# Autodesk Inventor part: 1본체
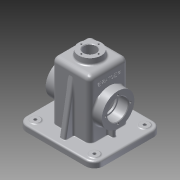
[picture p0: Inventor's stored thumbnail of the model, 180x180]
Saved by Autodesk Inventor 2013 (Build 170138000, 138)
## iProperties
Created: 2016-01
Part Number: 1본체
Material: 알루미늄 6061
Document SubType Name: Modeling
Designer: Administrator
Density: 2.71 g/cm^3
Mass: 867.692 g
Surface Area: 918.115 cm^2
Volume: 320.182 cm^3
Author: Administrator
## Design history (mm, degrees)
sketch "스케치1"
  geometry: L1 (-65, 57.5)-(65, 57.5); L2 (65, 57.5)-(65, -57.5); L3 (65, -57.5)-(-65, -57.5); L4 (-65, -57.5)-(-65, 57.5); 3 further points
  constraints: 8 end point, 2 midpoint, 2 parallel, 1 horizontal, 1 horizontal alignment, 1 perpendicular, 1 vertical alignment
  dimensions: "d0" = 130 distance of L1.start L1.end; "d2" = 115 distance of L1.end L2.end
extrude "돌출1" new body sketch "스케치1" distance "d3" = 10; taper "d4" = 0 deg
fillet "모깎기1" dims "d5" = 15
sketch "스케치2"
  geometry: L1 (-60, -52.5)-(60, -52.5); L2 (60, -52.5)-(60, 52.5); L3 (60, 52.5)-(-60, 52.5); L4 (-60, 52.5)-(-60, -52.5); 3 further points
  constraints: 8 end point, 2 midpoint, 2 parallel, 1 horizontal, 1 horizontal alignment, 1 perpendicular, 1 vertical alignment
  dimensions: "d6" = 105 distance of L3.end L1.start; "d8" = 120 distance of L2.end L3.end
extrude "돌출2" join sketch "스케치2" distance "d9" = 2; taper "d10" = 0 deg
fillet "모깎기2" dims "d11" = 10
sketch "스케치3"
  geometry: C1 r 7.5 at (-50, 42.5); C2 r 7.5 at (-50, -42.5); C3 r 7.5 at (50, -42.5); C4 r 7.5 at (50, 42.5); A1 r 15 centre (50, 42.5) between (65, 42.5) and (50, 57.5) reference; A2 r 15 centre (-50, 42.5) between (-50, 57.5) and (-65, 42.5) reference; A3 r 15 centre (-50, -42.5) between (-65, -42.5) and (-50, -57.5) reference; A4 r 15 centre (50, -42.5) between (50, -57.5) and (65, -42.5) reference; 1 further point
  constraints: 4 centre point, 4 coincident
  dimensions: "d12" = 15 diameter of C1; "d13" = 15 diameter of C2; "d14" = 15 diameter of C3; "d15" = 15 diameter of C4
extrude "돌출3" join sketch "스케치3" distance "d16" = 1; taper "d17" = 0 deg
hole "구멍1" diameter "d20" = 5; stored, may be unused: countersink angle "d24" = 90 deg, drill point angle "d26" = 118 deg; dims "d18" = 10, "d19" = 10, "d21" = 6, "d22" = 4, "d23" = 2, "d25" = 8
hole "구멍2" diameter "d29" = 5; stored, may be unused: countersink angle "d33" = 90 deg, drill point angle "d35" = 118 deg; dims "d27" = 10, "d28" = 10, "d30" = 6, "d31" = 4, "d32" = 2, "d34" = 8
hole "구멍3" diameter "d38" = 5; stored, may be unused: countersink angle "d42" = 90 deg, drill point angle "d44" = 118 deg; dims "d36" = 10, "d37" = 10, "d39" = 6, "d40" = 4, "d41" = 2, "d43" = 8
hole "구멍4" diameter "d47" = 5; stored, may be unused: countersink angle "d51" = 90 deg, drill point angle "d53" = 118 deg; dims "d45" = 10, "d46" = 10, "d48" = 6, "d49" = 4, "d50" = 2, "d52" = 8
sketch "스케치4"
  geometry: L1 (-32.5, 32.5)-(32.5, 32.5); L2 (32.5, 32.5)-(32.5, -32.5); L3 (32.5, -32.5)-(-32.5, -32.5); L4 (-32.5, -32.5)-(-32.5, 32.5); 3 further points
  constraints: 8 end point, 2 midpoint, 2 parallel, 1 horizontal, 1 horizontal alignment, 1 perpendicular, 1 vertical alignment
  dimensions: "d54" = 65 distance of L1.start L1.end; "d56" = 65 distance of L1.end L2.end
extrude "돌출4" join sketch "스케치4" distance "d57" = 98; taper "d58" = 0 deg
sketch "스케치6"
  geometry: C1 r 20 at (0, 0); 1 further point
  constraints: 2 coincident, 1 centre point
  dimensions: "d63" = 40 diameter of C1
extrude "돌출6" join sketch "스케치6" distance "d64" = 10; taper "d65" = -5 deg
fillet "모깎기3" dims "d66" = 8
fillet "모깎기4" dims "d67" = 8
sketch "스케치12"
  geometry: L1 (57.5, 10)-(57.5, 0) reference; L2 (57.5, 0)-(52.5, 0) reference; L3 (52.5, 0)-(52.5, -2) reference; L4 (52.5, -2)-(-52.5, -2) reference; L5 (-52.5, -2)-(-52.5, 0) reference; L6 (-52.5, 0)-(-57.5, 0) reference; L7 (-57.5, 0)-(-57.5, 10) reference; L8 (-57.5, 10)-(-32.5, 10) reference; L9 (-32.5, 10)-(-32.5, 100) reference; L10 (-24.5, 108)-(-20, 108) reference; L11 (-20, 108)-(-19.125, 118) reference; L12 (-19.125, 118)-(19.125, 118) reference; L13 (19.125, 118)-(20, 108) reference; L14 (20, 108)-(24.5, 108) reference; L15 (32.5, 100)-(32.5, 10) reference; L16 (32.5, 10)-(57.5, 10) reference; L17 (-31.102, 103)-(-47.5, 10); L18 (-31.102, 103)-(-31.102, 10); L19 (42.5, 10)-(-42.5, 10) reference; L20 (-57.5, 0)-(-57.5, 10) reference; A1 r 8 centre (-24.5, 100) between (-24.5, 108) and (-32.5, 100) reference; A2 r 8 centre (24.5, 100) between (32.5, 100) and (24.5, 108) reference; 1 further point
  constraints: 4 end point, 2 point on line, 1 vertical
  dimensions: "d122" = 10 distance of L17.end L7.end; "d123" = 10 deg angle of L17 L20; "d124" = 93 distance of L17.start L18.end
extrude "돌출9" join sketch "스케치12" stored distance "d125" = 10; taper "d126" = 0 deg
sketch "스케치7"
  geometry: L1 (27.5, -27.5)-(-27.5, -27.5); L2 (-27.5, -27.5)-(-27.5, 27.5); L3 (-27.5, 27.5)-(27.5, 27.5); L4 (27.5, 27.5)-(27.5, -27.5); 3 further points
  constraints: 8 end point, 2 midpoint, 2 parallel, 1 horizontal, 1 horizontal alignment, 1 perpendicular, 1 vertical alignment
  dimensions: "d68" = 55 distance of L1.end L2.end; "d70" = 55 distance of L1.start L1.end
extrude "돌출7" cut sketch "스케치7" distance "d71" = 105; taper "d72" = 0 deg
fillet "모깎기5" dims "d73" = 3
fillet "모깎기6" dims "d74" = 3
hole "구멍5" diameter "d77" = 21; stored, may be unused: countersink angle "d81" = 90 deg, drill point angle "d83" = 118 deg; dims "d75" = 10, "d76" = 10, "d78" = 6, "d79" = 4, "d80" = 2, "d82" = 8
sketch "스케치8"
  geometry: L1 (12, 67)-(12, -18) reference; L2 (0, -18)-(0, 67) reference; C1 r 27.5 at (-43, 24.5); 2 further points
  constraints: 1 centre point, 1 horizontal alignment, 1 midpoint
  dimensions: "d84" = 55 diameter of C1; "d156" = 55 distance from line of L1 C1.centre
extrude "돌출8" join sketch "스케치8" distance "d85" = 15; taper "d86" = 0 deg
hole "구멍6" diameter "d89" = 30; stored, may be unused: countersink angle "d93" = 90 deg, drill point angle "d95" = 0 deg; dims "d87" = 10, "d88" = 10, "d90" = 6, "d91" = 35, "d92" = 17, "d94" = 20
sketch "스케치9"
  geometry: C1 r 17.5 at (0, 0) reference; 2 further points
  constraints: 1 horizontal alignment
  dimensions: "d96" = 21 distance of C1.centre point (21, 0)
hole "구멍7" sketch "스케치9" at (21, 0) diameter "d97" = 3.242; stored, may be unused: countersink angle "d101" = 90 deg, drill point angle "d103" = 118 deg; dims "d98" = 8, "d99" = 35, "d100" = 17, "d102" = 10
sketch "스케치10"
  geometry: C1 r 10.5 at (0, 0) reference; 1 further point
  constraints: 1 horizontal alignment
  dimensions: "d107" = 14.5 distance of C1.centre point (-14.5, 0)
hole "구멍8" sketch "스케치10" at (-14.5, 0) diameter "d108" = 2.459; stored, may be unused: countersink angle "d112" = 90 deg, drill point angle "d114" = 118 deg; dims "d109" = 7, "d110" = 35, "d111" = 17, "d113" = 9
sketch "스케치14"
  geometry: L1 (-18, 5.375)-(-18, 43.625) reference; A1 r 27.5 centre (47, 24.5) between (34.51, 49) and (34.51, 0) reference; 2 further points
  constraints: 1 horizontal alignment, 1 other
  dimensions: "d131" = 27 distance from line of L1 point (9, 24.5)
feature "엠보싱1" sketch "스케치14" dims "d132" = 0.5, "d133" = 0
chamfer "모따기1" distance "d134" = 1; stored, may be unused: second distance "d135" = 2, angle "d136" = 45 deg
fillet "모깎기7" dims "d137" = 0.3
fillet "모깎기8" dims "d138" = 3
fillet "모깎기9" dims "d139" = 3
fillet "모깎기10" dims "d140" = 3
sketch "스케치15"
  geometry: L1 (-27.5, 100)-(-27.5, 68) reference; L2 (-27.5, 68)-(-30.5, 68) reference; L3 (-30.5, 68)-(-30.5, 70.2) reference; L4 (-30.8, 70.5)-(-46.5, 70.5) reference; L5 (-46.5, 70.5)-(-47.5, 71.5) reference; L6 (-47.5, 71.5)-(-47.5, 72.379) reference; L7 (-47.5, 72.379)-(-37.5, 72.379) reference; L8 (-37.5, 72.379)-(-36.526, 74) reference; L9 (-36.526, 74)-(-37.5, 75.621) reference; L10 (-37.5, 75.621)-(-47.5, 75.621) reference; L11 (-47.5, 75.621)-(-47.5, 80.5) reference; L12 (-47.5, 80.5)-(-32.5, 80.5) reference; L13 (-32.5, 80.5)-(-32.5, 92.971) reference; L14 (-32.5, 92.971)-(-33, 92.971) reference; L15 (-33, 92.971)-(-33, 93.385) reference; L16 (-33, 93.385)-(-32.5, 93.385) reference; L17 (-32.5, 93.385)-(-32.5, 100) reference; L18 (-24.5, 108)-(-20, 108) reference; L19 (-20, 108)-(-19.125, 118) reference; L20 (-19.125, 118)-(-15.73, 118) reference; L21 (-15.73, 118)-(-15.73, 109) reference; L22 (-15.73, 109)-(-14.5, 108.261) reference; L23 (-14.5, 108.261)-(-13.271, 109) reference; L24 (-13.271, 109)-(-13.271, 118) reference; L25 (-13.271, 118)-(-11.5, 118) reference; L26 (-11.5, 118)-(-10.5, 117) reference; L27 (-10.5, 117)-(-10.5, 103) reference; L28 (-10.5, 103)-(-24.5, 103) reference; L29 (24.5, 103)-(10.5, 103) reference; L30 (10.5, 103)-(10.5, 117) reference; L31 (10.5, 117)-(11.5, 118) reference; L32 (11.5, 118)-(13.271, 118) reference; L33 (13.271, 118)-(13.271, 109) reference; L34 (13.271, 109)-(14.5, 108.261) reference; L35 (14.5, 108.261)-(15.73, 109) reference; L36 (15.73, 109)-(15.73, 118) reference; L37 (15.73, 118)-(19.125, 118) reference; L38 (19.125, 118)-(20, 108) reference; L39 (20, 108)-(24.5, 108) reference; L40 (32.5, 100)-(32.5, 80.5) reference; L41 (32.5, 80.5)-(47.5, 80.5) reference; L42 (47.5, 80.5)-(47.5, 75.621) reference; L43 (47.5, 75.621)-(37.5, 75.621) reference; L44 (37.5, 75.621)-(36.526, 74) reference; L45 (36.526, 74)-(37.5, 72.379) reference; L46 (37.5, 72.379)-(47.5, 72.379) reference; L47 (47.5, 72.379)-(47.5, 71.5) reference; L48 (47.5, 71.5)-(46.5, 70.5) reference; L49 (46.5, 70.5)-(30.8, 70.5) reference; L50 (30.5, 70.2)-(30.5, 68) reference; L51 (30.5, 68)-(27.5, 68) reference; L52 (27.5, 68)-(27.5, 100) reference; L53 (-60, -2)-(-60, 0) reference; L54 (-60, 0)-(-65, 0) reference; L55 (-65, 0)-(-65, 7) reference; L56 (-62, 10)-(-32.5, 10) reference; L57 (-32.5, 10)-(-32.5, 25.5) reference; L58 (-32.5, 25.5)-(-47.5, 25.5) reference; L59 (-47.5, 25.5)-(-47.5, 30.379) reference; L60 (-47.5, 30.379)-(-37.5, 30.379) reference; L61 (-37.5, 30.379)-(-36.526, 32) reference; L62 (-36.526, 32)-(-37.5, 33.621) reference; L63 (-37.5, 33.621)-(-47.5, 33.621) reference; L64 (-47.5, 33.621)-(-47.5, 34.5) reference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; A1 r 3 centre (-24.5, 100) between (-24.5, 103) and (-27.5, 100) reference; A2 r 0.3 centre (-30.8, 70.2) between (-30.5, 70.2) and (-30.8, 70.5) reference; A3 r 8 centre (-24.5, 100) between (-24.5, 108) and (-32.5, 100) reference; A4 r 3 centre (24.5, 100) between (27.5, 100) and (24.5, 103) reference; A5 r 8 centre (24.5, 100) between (32.5, 100) and (24.5, 108) reference; A6 r 0.3 centre (30.8, 70.2) between (30.8, 70.5) and (30.5, 70.2) reference; A7 r 3 centre (-62, 7) between (-62, 10) and (-65, 7) reference; A8 r 0.3 centre (-30.8, 35.8) between (-30.8, 35.5) and (-30.5, 35.8) reference; A9 r 0.3 centre (30.8, 35.8) between (30.5, 35.8) and (30.8, 35.5) reference; A10 r 3 centre (62, 7) between (65, 7) and (62, 10) reference; 1 further point
  constraints: 2 end point, 2 point on line, 1 vertical
  dimensions: "d142" = 15 distance between parallel lines of L89 L69
feature "리브1" sketch "스케치15" dims "d143" = 1, "d144" = 6, "d145" = 0, "d146" = 0, "d147" = 1, "d148" = 1
fillet "모깎기11" dims "d149" = 3
fillet "모깎기12" dims "d150" = 3
fillet "모깎기13" dims "d151" = 3
fillet "모깎기14" dims "d152" = 1
fillet "모깎기15" dims "d153" = 3
fillet "모깎기16" dims "d154" = 3
node "솔리드1"
mirror "대칭3"
mirror "대칭1"
pattern_circular "원형 패턴1" dims angle "d105" = 360 deg
mirror "대칭2"
pattern_circular "원형 패턴2" dims angle "d116" = 360 deg
mirror "대칭4"
node "절단 모서리 투영2"
node "절단 모서리 투영4"
